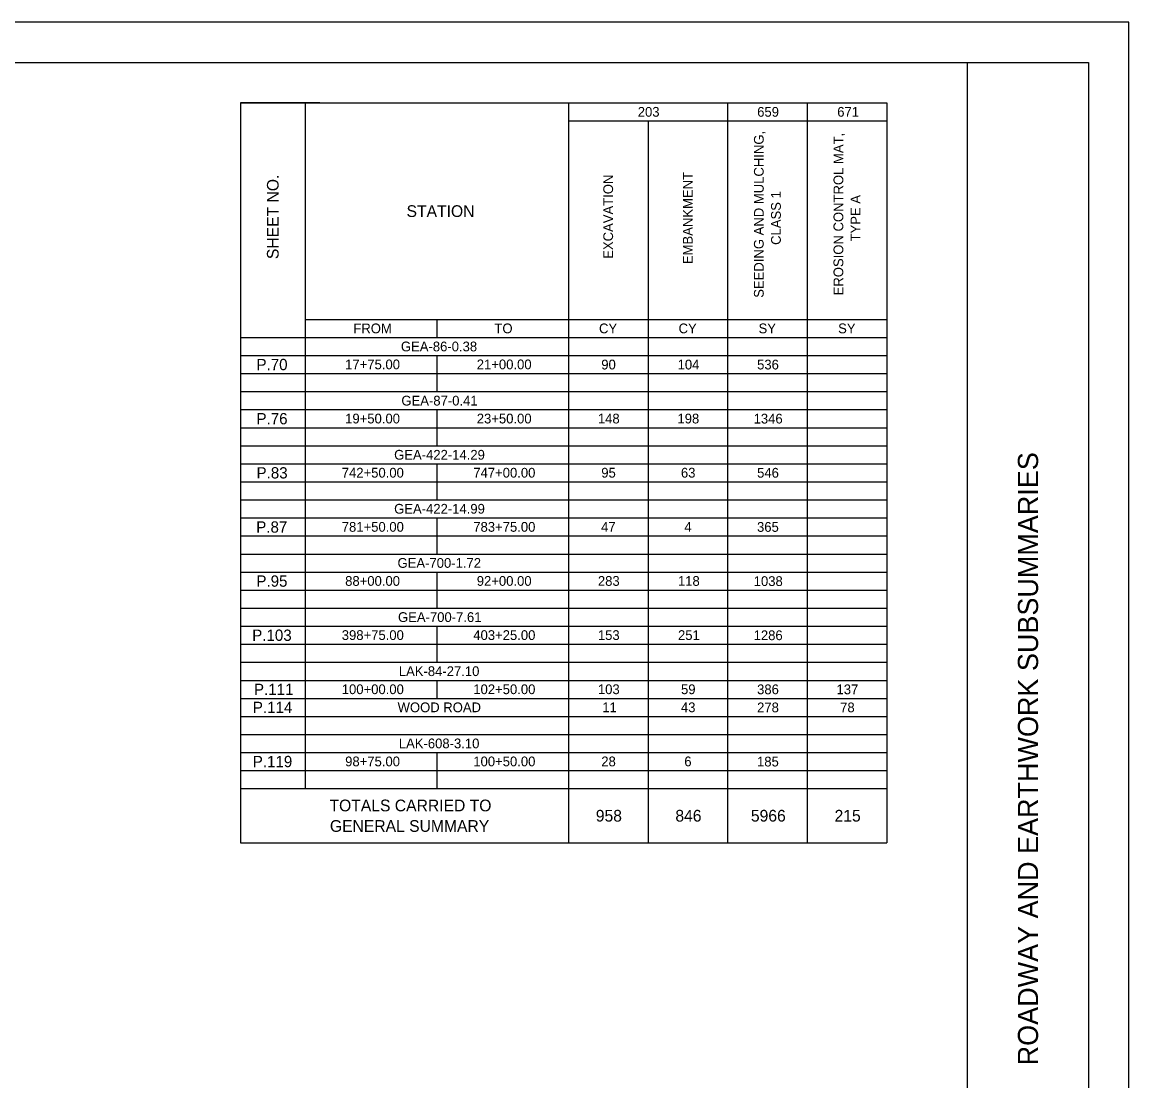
# Model space of a CAD drawing. Extents: x 0 to 34, y 0 to 22.
# Drawn here: x 20.29 to 34, y 8.88 to 22 of the extents above; entities that cross this region are included whole.
import ezdxf

# ---------------------------------------------------------------- set-up
doc = ezdxf.new("R2010")
doc.units = 0
for name, color, linetype in [('SH_Border', 7, 'Continuous'), ('SH_Cut_Line', 7, 'Continuous'), ('SH_Data', 7, 'Continuous'), ('SH_Text', 7, 'Continuous')]:
    doc.layers.add(name, color=color, linetype=linetype)

msp = doc.modelspace()

# ---------------------------------------------------------------- linework, layer by layer
at = {"layer": 'SH_Border'}
msp.add_line((32, 0.5), (32, 21.5), dxfattribs=at)
msp.add_lwpolyline([(1.5, 21.5), (33.5, 21.5), (33.5, 0.5), (1.5, 0.5)], close=True, dxfattribs=at)
at = {"layer": 'SH_Cut_Line'}
msp.add_lwpolyline([(0, 0), (34, 0), (34, 22), (0, 22)], close=True, dxfattribs=at)
at = {"layer": 'SH_Text'}
for p, q in [((22.99, 21), (31, 21)), ((22.99, 21), (22.99, 11.833)), ((23.792, 21), (23.792, 12.503)), ((27.054, 21), (27.054, 11.833)), ((29.027, 21), (29.027, 11.833)), ((30.014, 21), (30.014, 11.833)), ((31, 21), (31, 11.833)), ((27.054, 20.776), (31, 20.776)), ((28.041, 20.776), (28.041, 11.833)), ((23.792, 18.317), (31, 18.317)), ((25.423, 18.317), (25.423, 18.093)), ((22.99, 18.093), (31, 18.093)), ((22.99, 17.87), (31, 17.87)), ((25.423, 17.87), (25.423, 17.422)), ((22.99, 17.646), (31, 17.646)), ((22.99, 17.422), (31, 17.422)), ((22.99, 17.199), (31, 17.199)), ((25.423, 17.199), (25.423, 16.752)), ((22.99, 16.975), (31, 16.975)), ((22.99, 16.752), (31, 16.752)), ((22.99, 16.528), (31, 16.528)), ((25.423, 16.528), (25.423, 16.081)), ((22.99, 16.304), (31, 16.304)), ((22.99, 16.081), (31, 16.081)), ((22.99, 15.857), (31, 15.857)), ((25.423, 15.857), (25.423, 15.41)), ((22.99, 15.634), (31, 15.634)), ((22.99, 15.41), (31, 15.41)), ((22.99, 15.187), (31, 15.187)), ((25.423, 15.187), (25.423, 14.739)), ((22.99, 14.963), (31, 14.963)), ((22.99, 14.739), (31, 14.739)), ((22.99, 14.516), (31, 14.516)), ((25.423, 14.516), (25.423, 14.069)), ((22.99, 14.292), (31, 14.292)), ((22.99, 14.069), (31, 14.069)), ((22.99, 13.845), (31, 13.845)), ((25.423, 13.845), (25.423, 13.621)), ((22.99, 13.621), (31, 13.621)), ((22.99, 13.398), (31, 13.398)), ((22.99, 13.174), (31, 13.174)), ((22.99, 12.951), (31, 12.951)), ((25.423, 12.951), (25.423, 12.503)), ((22.99, 12.727), (31, 12.727)), ((22.99, 12.503), (31, 12.503)), ((22.99, 11.833), (31, 11.833))]:
    msp.add_line(p, q, dxfattribs=at)
for points in [[(22.99, 21), (22.99, 21), (22.99, 21), (22.99, 21)], [(22.99, 21), (23.976, 21), (23.976, 21), (22.99, 21)], [(22.99, 21), (23.976, 21), (23.976, 21), (22.99, 21)], [(22.99, 21), (23.976, 21), (23.976, 21), (22.99, 21)], [(22.99, 21), (23.976, 21), (23.976, 21), (22.99, 21)], [(22.99, 21), (22.99, 21), (22.99, 21), (22.99, 21)], [(22.99, 21), (23.976, 21), (23.976, 21), (22.99, 21)], [(22.99, 21), (23.976, 21), (23.976, 21), (22.99, 21)], [(22.99, 21), (23.976, 21), (23.976, 21), (22.99, 21)], [(22.99, 21), (23.976, 21), (23.976, 21), (22.99, 21)], [(22.99, 21), (22.99, 21), (22.99, 21), (22.99, 21)], [(22.99, 21), (23.976, 21), (23.976, 21), (22.99, 21)], [(22.99, 21), (23.976, 21), (23.976, 21), (22.99, 21)], [(22.99, 21), (23.976, 21), (23.976, 21), (22.99, 21)], [(22.99, 21), (23.976, 21), (23.976, 21), (22.99, 21)]]:
    msp.add_lwpolyline(points, close=True, dxfattribs=at)

# ---------------------------------------------------------------- texts
at = {"layer": 'SH_Data'}
msp.add_text('ROADWAY AND EARTHWORK SUBSUMMARIES', height=0.25, rotation=90, dxfattribs=at).set_placement((32.875, 9.075))
at = {"layer": 'SH_Text'}
for s, height, p in [('203', 0.121, (27.914, 20.828)), ('659', 0.121, (29.394, 20.828)), ('671', 0.121, (30.386, 20.828)), ('STATION', 0.1452, (25.049, 19.586)), ('FROM', 0.121, (24.39, 18.145)), ('TO', 0.121, (26.138, 18.145)), ('CY', 0.121, (27.434, 18.145)), ('CY', 0.121, (28.42, 18.145)), ('SY', 0.121, (29.411, 18.145)), ('SY', 0.121, (30.397, 18.145)), ('GEA-86-0.38', 0.121, (24.979, 17.921)), ('P.70', 0.14, (23.189, 17.688)), ('17+75.00', 0.121, (24.288, 17.699)), ('21+00.00', 0.121, (25.919, 17.699)), ('90', 0.121, (27.462, 17.697)), ('104', 0.121, (28.408, 17.697)), ('536', 0.121, (29.393, 17.697)), ('GEA-87-0.41', 0.121, (24.985, 17.25)), ('P.76', 0.14, (23.189, 17.017)), ('19+50.00', 0.121, (24.288, 17.028)), ('23+50.00', 0.121, (25.919, 17.028)), ('148', 0.121, (27.42, 17.028)), ('198', 0.121, (28.406, 17.028)), ('1346', 0.121, (29.35, 17.027)), ('GEA-422-14.29', 0.121, (24.895, 16.579)), ('P.83', 0.14, (23.19, 16.346)), ('742+50.00', 0.121, (24.246, 16.357)), ('747+00.00', 0.121, (25.876, 16.357)), ('95', 0.121, (27.462, 16.357)), ('63', 0.121, (28.449, 16.357)), ('546', 0.121, (29.393, 16.356)), ('GEA-422-14.99', 0.121, (24.895, 15.91)), ('P.87', 0.14, (23.186, 15.675)), ('781+50.00', 0.121, (24.246, 15.686)), ('783+75.00', 0.121, (25.876, 15.686)), ('47', 0.121, (27.46, 15.686)), ('4', 0.121, (28.492, 15.686)), ('365', 0.121, (29.392, 15.685)), ('GEA-700-1.72', 0.121, (24.937, 15.239)), ('P.95', 0.14, (23.188, 15.005)), ('88+00.00', 0.121, (24.288, 15.016)), ('92+00.00', 0.121, (25.919, 15.016)), ('283', 0.121, (27.42, 15.016)), ('118', 0.121, (28.412, 15.016)), ('1038', 0.121, (29.351, 15.014)), ('GEA-700-7.61', 0.121, (24.943, 14.568)), ('P.103', 0.14, (23.136, 14.334)), ('398+75.00', 0.121, (24.246, 14.345)), ('403+25.00', 0.121, (25.876, 14.345)), ('153', 0.121, (27.42, 14.345)), ('251', 0.121, (28.413, 14.345)), ('1286', 0.121, (29.35, 14.343)), ('LAK-84-27.10', 0.121, (24.953, 13.898)), ('P.111', 0.14, (23.158, 13.663)), ('100+00.00', 0.121, (24.246, 13.674)), ('102+50.00', 0.121, (25.876, 13.674)), ('103', 0.121, (27.42, 13.674)), ('59', 0.121, (28.45, 13.674)), ('386', 0.121, (29.393, 13.673)), ('137', 0.121, (30.377, 13.673)), ('P.114', 0.14, (23.144, 13.44)), ('WOOD ROAD', 0.121, (24.938, 13.45)), ('11', 0.121, (27.474, 13.45)), ('43', 0.121, (28.449, 13.45)), ('278', 0.121, (29.393, 13.449)), ('78', 0.121, (30.422, 13.449)), ('LAK-608-3.10', 0.121, (24.953, 13.003)), ('P.119', 0.14, (23.143, 12.769)), ('98+75.00', 0.121, (24.288, 12.78)), ('100+50.00', 0.121, (25.876, 12.78)), ('28', 0.121, (27.462, 12.78)), ('6', 0.121, (28.491, 12.78)), ('185', 0.121, (29.392, 12.778)), ('TOTALS CARRIED TO', 0.14521, (24.094, 12.222)), ('958', 0.1452, (27.394, 12.095)), ('846', 0.1452, (28.38, 12.095)), ('5966', 0.1452, (29.316, 12.095)), ('215', 0.1452, (30.353, 12.095)), ('GENERAL SUMMARY', 0.14521, (24.099, 11.968))]:
    msp.add_text(s, height=height, dxfattribs=at).set_placement(p)
for s, height, p in [('SEEDING AND MULCHING,', 0.121, (29.475, 18.585)), ('EROSION CONTROL MAT,', 0.121, (30.461, 18.615)), ('SHEET NO.', 0.1452, (23.464, 19.064)), ('EXCAVATION', 0.121, (27.608, 19.068)), ('EMBANKMENT', 0.121, (28.594, 19.002)), ('CLASS 1', 0.121, (29.687, 19.24)), ('TYPE A', 0.121, (30.673, 19.283))]:
    msp.add_text(s, height=height, rotation=90, dxfattribs=at).set_placement(p)

doc.saveas('drawing.dxf')
